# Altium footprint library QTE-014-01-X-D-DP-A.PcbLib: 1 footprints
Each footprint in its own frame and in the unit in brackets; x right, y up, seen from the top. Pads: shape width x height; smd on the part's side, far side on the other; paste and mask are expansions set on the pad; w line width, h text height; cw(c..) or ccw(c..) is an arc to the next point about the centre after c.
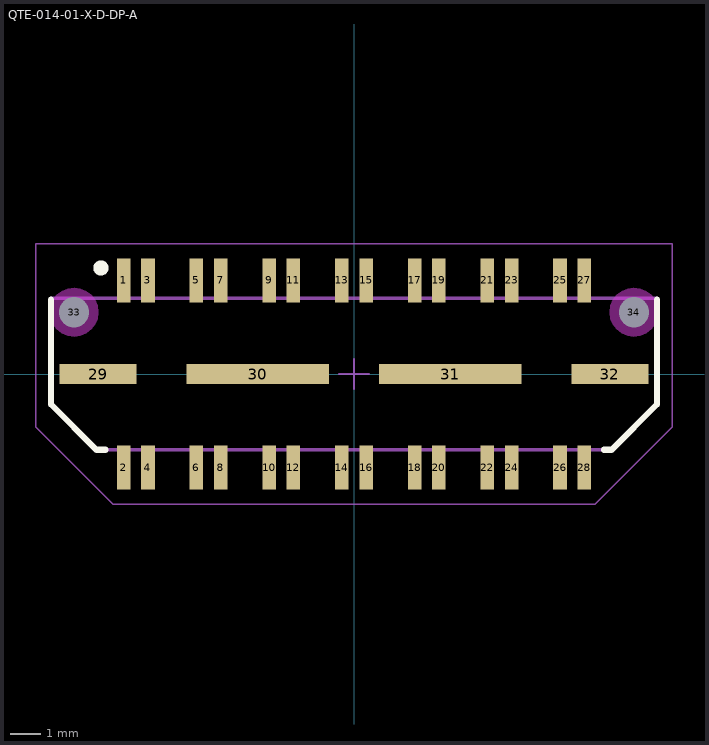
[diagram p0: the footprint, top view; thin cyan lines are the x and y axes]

## QTE-014-01-X-D-DP-A [mm] "0.80mm pitch, 28 pin, high speed terminal strip, differential"
height 4.27
pads (34):
  rect 0.45x1.45 smd mask+0: 1(-7.6,3.09) 2(-7.6,-3.09) 3(-6.8,3.09) 4(-6.8,-3.09) 5(-5.2,3.09) 6(-5.2,-3.09) 7(-4.4,3.09) 8(-4.4,-3.09) 9(-2.8,3.09) 10(-2.8,-3.09) 11(-2,3.09) 12(-2,-3.09) 13(-0.4,3.09) 14(-0.4,-3.09) 15(0.4,3.09) 16(0.4,-3.09) 17(2,3.09) 18(2,-3.09) 19(2.8,3.09) 20(2.8,-3.09) 21(4.4,3.09) 22(4.4,-3.09) 23(5.2,3.09) 24(5.2,-3.09) 25(6.8,3.09) 26(6.8,-3.09) 27(7.6,3.09) 28(7.6,-3.09)
  rect 2.55x0.65 smd mask+0: 29(-8.445,0) 32(8.445,0)
  rect 4.7x0.65 smd mask+0: 30(-3.175,0) 31(3.175,0)
  round 0.5 hole 1 unplated mask+0: 33(-9.24,2.04) 34(9.24,2.04)
Top Overlay:
  circle w0.25: c-8.35,3.5 r0.125
  lines w0.2: -10,2.45 -10,-1 -8.5,-2.5 -8.2,-2.5 ; 8.25,-2.5 8.5,-2.5 10,-1 10,2.45
Keep-Out Layer:
  pour cut-out: -8.433,2.04 -8.461,2.249 -8.541,2.443 -8.669,2.611 -8.837,2.739 -9.031,2.819 -9.24,2.847 -9.449,2.819 -9.643,2.739 -9.811,2.611 -9.939,2.443 -10.019,2.249 -10.047,2.04 -10.019,1.831 -9.939,1.637 -9.811,1.469 -9.643,1.341 -9.449,1.261 -9.24,1.233 -9.031,1.261 -8.837,1.341 -8.669,1.469 -8.541,1.637 -8.461,1.831
  pour cut-out: 10.047,2.04 10.019,2.249 9.939,2.443 9.811,2.611 9.643,2.739 9.449,2.819 9.24,2.847 9.031,2.819 8.837,2.739 8.669,2.611 8.541,2.443 8.461,2.249 8.433,2.04 8.461,1.831 8.541,1.637 8.669,1.469 8.837,1.341 9.031,1.261 9.24,1.233 9.449,1.261 9.643,1.341 9.811,1.469 9.939,1.637 10.019,1.831
Mechanical 13:
  lines w0.01: -10,-1 -8.5,-2.5 8.5,-2.5 10,-1 10,2.5 -10,2.5 -10,-1
  lines w0.1: -10,-1 -8.5,-2.5 8.5,-2.5 10,-1 10,2.5 -10,2.5 -10,-1
  text ".Designator" at 0.254,0.254 h1.52
Mechanical 15:
  lines w0.05: -0.5,0 0.5,0 ; 0,-0.5 0,0.5 ; -10.5,-1.75 -7.95,-4.3 7.95,-4.3 10.5,-1.75 10.5,4.3 -10.5,4.3 -10.5,-1.75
